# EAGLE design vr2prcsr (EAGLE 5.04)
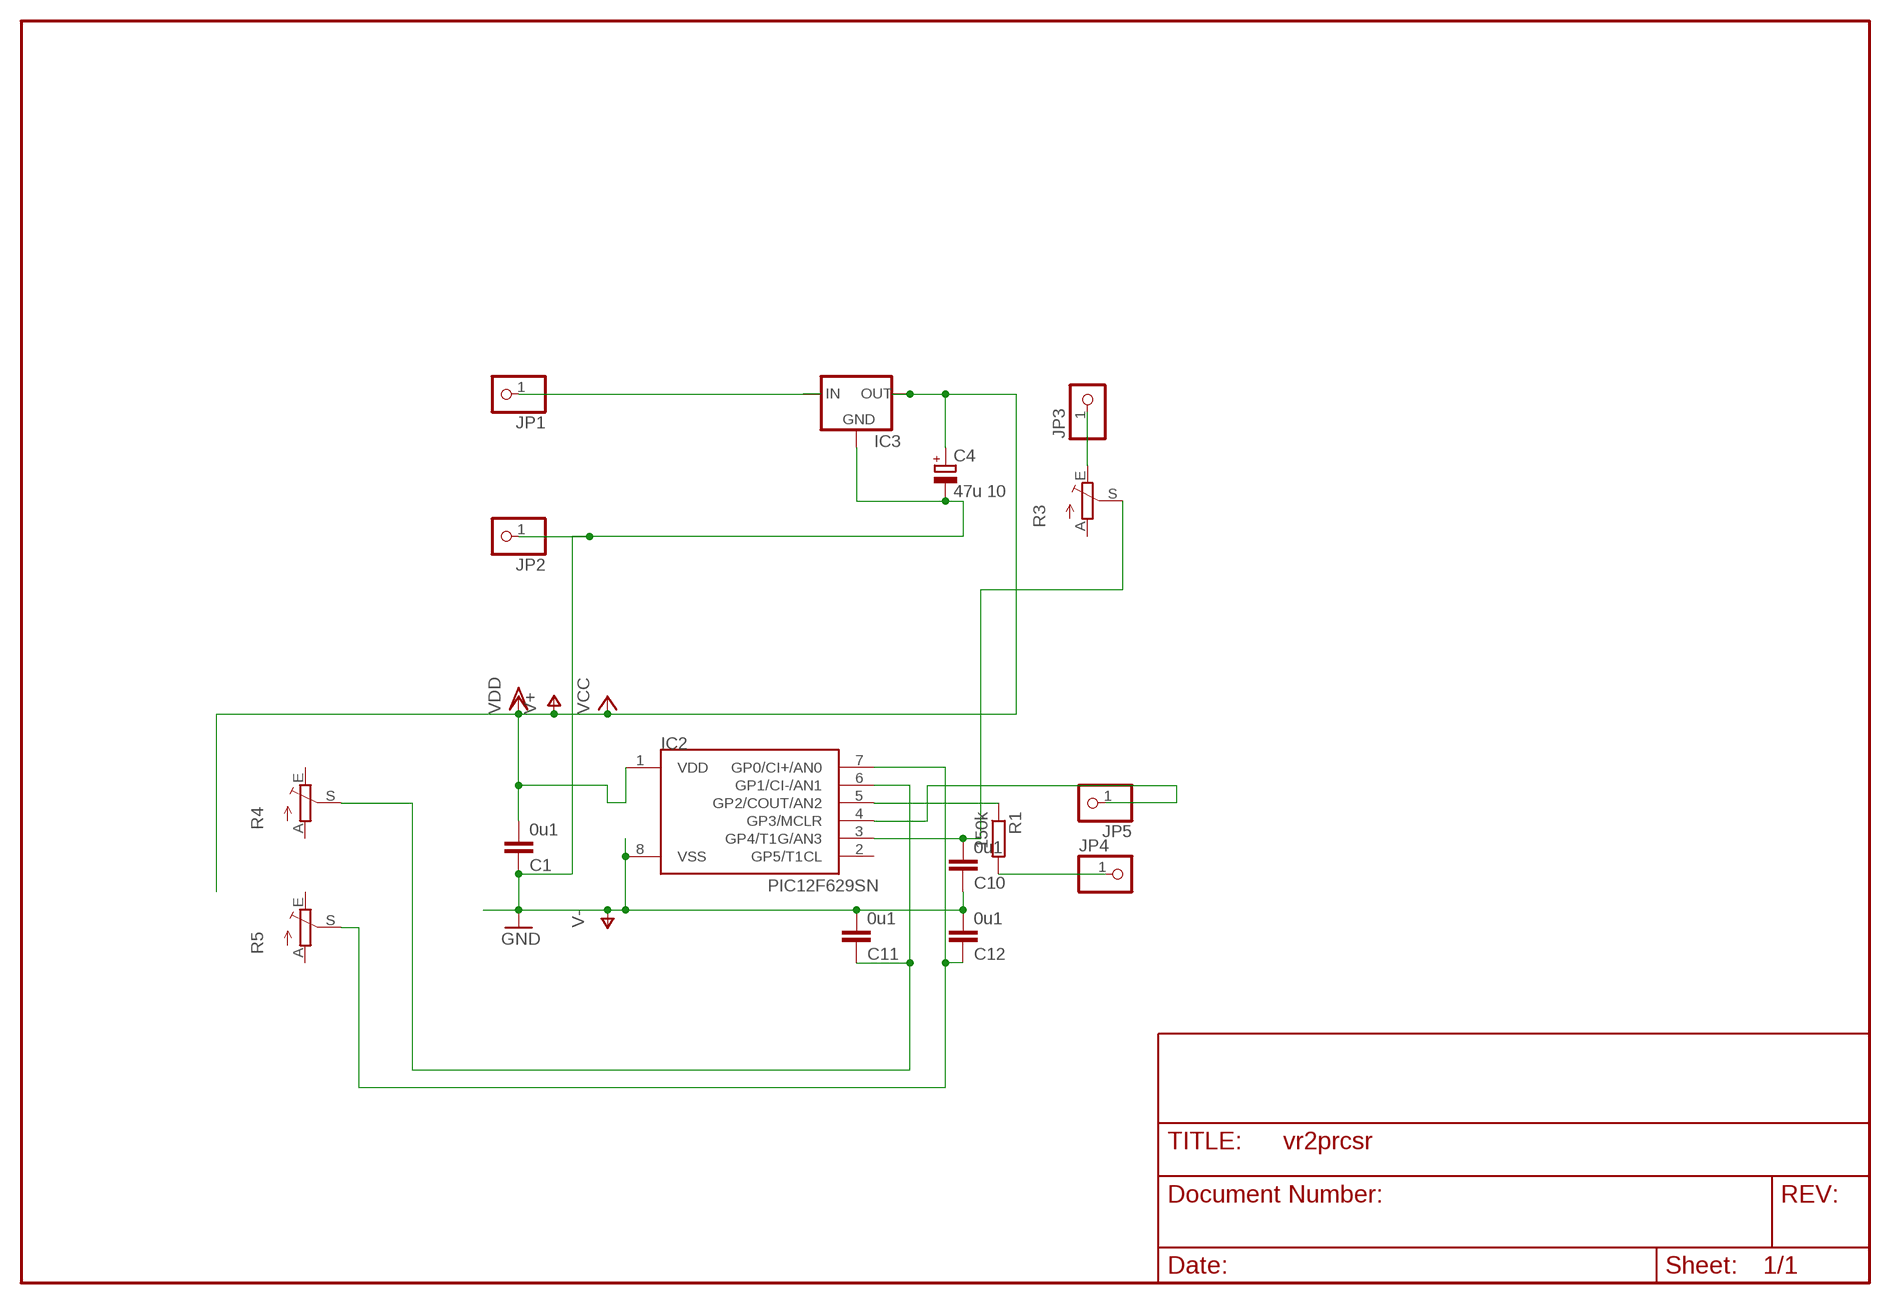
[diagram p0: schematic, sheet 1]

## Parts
C1  0u1  C-EUC1206  [C1206]
C4  47u 10  CPOL-EUE2.5-6  [E2,5-6]
C10  0u1  C-EUC1206  [C1206]
C11  0u1  C-EUC1206  [C1206]
C12  0u1  C-EUC1206  [C1206]
IC2  PIC12F629SN  [SO-08]
IC3  78LXX  [78LXX]
JP1  PINHD-1X1  [1X01]
JP2  PINHD-1X1  [1X01]
JP3  PINHD-1X1  [1X01]
JP4  PINHD-1X1  [1X01]
JP5  PINHD-1X1  [1X01]
R1  150k  R-EU_R1206  [R1206]
R3  TRIM_EU-CA6V  [CA6V]
R4  TRIM_EU-CA6V  [CA6V]
R5  TRIM_EU-CA6V  [CA6V]

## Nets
N$1: JP3.1 R3.E
N$2: JP4.1 R1.2
N$3: IC2.4(GP3/MCLR) JP5.1
N$5: IC2.5(GP2/COUT/AN2) R1.1
N$12: C10.2 IC2.3(GP4/T1G/AN3) R3.S
N$13: C12.1 IC2.7(GP0/CI+/AN0) R5.S
N$15: C11.1 IC2.6(GP1/CI-/AN1) R4.S
N$20: IC3.IN JP1.1
V+: C1.2 C4.+ IC2.1(VDD) IC3.OUT ; supply symbol labelled VCC, VDD
V-: C1.1 C4.- C10.1 C11.2 C12.2 IC2.8(VSS) IC3.GND JP2.1 ; supply symbol labelled GND
Unconnected: IC2.2(GP5/T1CL) R3.A R4.A R4.E R5.A R5.E

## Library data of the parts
C1 C10-C12 = rcl:C-EU: CAPACITOR, European symbol
C4 = rcl:CPOL-EU: POLARIZED CAPACITOR, European symbol
IC2 = microchip-3:PIC12F6*: uPC nW 1k Program Flash memory 2x Timer Comparator 10b A/D converter/ 4xIN
IC3 = v-reg:78LXX: VOLTAGE REGULATOR
JP1-JP5 = pinhead:PINHD-1X1: PIN HEADER
R1 = rcl:R-EU_: RESISTOR, European symbol
R3-R5 = pot:TRIM_EU-: POTENTIOMETER

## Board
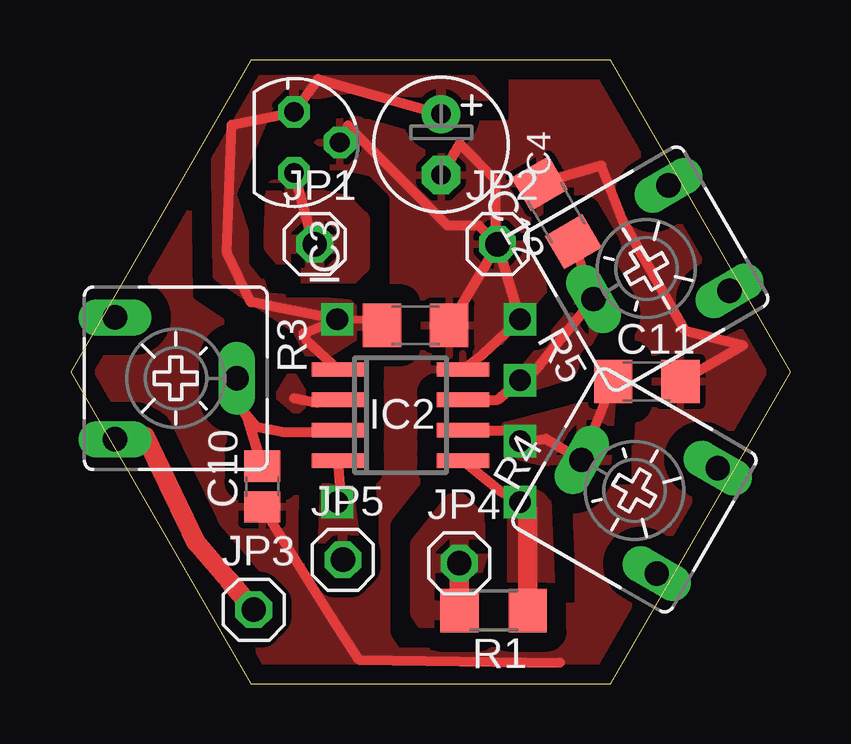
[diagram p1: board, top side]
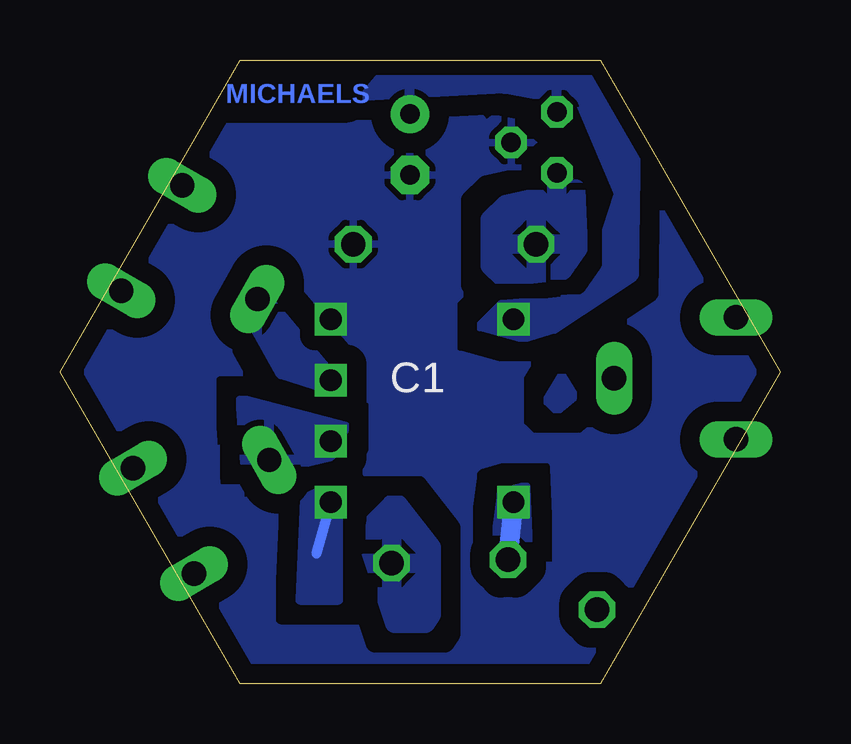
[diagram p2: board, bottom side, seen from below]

Size 30 x 26 mm. Coordinates in mm from the lower left corner, seen from the top.
Outline: 7.5,0 22.5,0 30,13 22.5,26 7.5,26 0,13 7.5,0
Copper layers (1*16): Top 0.035mm / dielectric 1.5mm / Bottom 0.035mm
Design rules "default *": minimum track width 10mil, minimum drill 24mil, track to track 8mil, track to pad 8mil, pad to pad 8mil, via to via 8mil, smd to smd 8mil, copper to edge 10mil, drill to drill 8mil, minimum pad ring 10mil, minimum via ring 8mil, stop-mask expansion 4mil, vias tented up to drill 0mil, thermal gap 10mil

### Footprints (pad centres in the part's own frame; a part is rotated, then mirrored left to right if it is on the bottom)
C1206 = smd 1.6 x 1.8: 1 -1.4,0; 2 1.4,0
E2,5-6 = drill 0.813 pad 1.6 round: + -1.27,0 | drill 0.813 pad 1.6 octagon: - 1.27,0
C0805 = smd 1.3 x 1.5: 1 -0.85,0; 2 0.85,0
SO-08 = smd 0.6 x 2.2: 1 -1.905,-2.6; 2 -0.635,-2.6; 3 0.635,-2.6; 4 1.905,-2.6; 5 1.905,2.6; 6 0.635,2.6; 7 -0.635,2.6; 8 -1.905,2.6
78LXX = drill 0.813 octagon: GND 0,1.905; IN 1.27,0; OUT -1.27,0
1X01 = drill 1.016 octagon: 1 0,0
R1206 = smd 1.6 x 1.803: 1 -1.422,0; 2 1.422,0
CA6V = drill 1.016 long: A -2.54,-2.54; E 2.54,-2.54; S 0,2.54

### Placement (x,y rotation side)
C1  14.36,14.94 180 top
C4  15.42,22.47 270 top
C10  0u1  [C0805]  7.97,8.21 90 top
C11  24,12.59 0 top
C12  20.23,19.63 120 top
IC2  13.74,11.19 270 top
IC3  9.3,22.56 270 top
JP1  10.16,18.32 0 top
JP2  17.78,18.32 0 top
JP3  7.62,3.08 0 top
JP4  16.18,5.02 0 top
JP5  11.33,5.16 0 top
R1  17.61,3.05 180 top
R3  4.37,12.73 270 top
R4  23.48,8.05 60 top
R5  23.98,17.3 120 top

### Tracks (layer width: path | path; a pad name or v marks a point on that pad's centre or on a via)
N$1
  Top 0.406: R3.E 3.1,10.3
  Top 0.813: 3.1,10.3 5.2,5.9 6.6,4.28 JP3.1
N$2
  Top 0.813: R1.2 JP4.1
  pour Top (isolate 0.813): 16.05,2.61 14.78,2.61 14.53,2.99 14.53,5.78 15.93,7.56 16.18,7.56 17.32,6.42
  pour Bottom (isolate 0.813): 16.05,2.51 14.78,2.51 14.53,2.89 14.53,5.68 15.93,7.46 16.18,7.46 17.32,6.32
N$3  (via drill 0.9)
  Top 0.406: IC2.4 11.26,7.72 v11.1,7.56
  Bottom 0.406: JP5.1 11.3,5.59
  Bottom 0.813: 11.3,5.59 v11.1,7.56
  pour Top (isolate 0.61): 10.6,8.2 11.6,7.9 11.9,5.6 11.3,5.4 10.5,5.7
  pour Bottom (isolate 0.61): 10.6,8.2 11.6,7.9 11.9,5.6 11.3,5.4 10.5,5.7
N$4
  pour Bottom (isolate 0.254): 9.7,11.8 9.3,11.4 8.6,12 9.1,12.8
N$5  (via drill 0.9)
  Top 0.406: IC2.5 17.88,8.02 v18.72,7.56
  Top 0.813: R1.1 19.04,7.24 v18.72,7.56
  Bottom 0.406: v18.72,7.56 19.32,5.42
  pour Top (isolate 0.61): 19,8.1 19.8,7.7 20,3.5 18.4,3.5 18.4,7
  pour Bottom (isolate 0.61): 19,8.1 19.8,7.7 20,3.5 18.4,3.5 18.4,7
N$7
  Top 0.406: 9.3,11.9 10.3,11.7
  pour Top (isolate 0.254): 9.8,11.8 9.4,11.4 8.7,12 9.2,12.8
N$12
  Top 0.406: 7.06,11.49 7.7,10.72 8.86,10.48 11.06,10.48 IC2.3 | 7.06,11.49 R3.S | C10.2 7.37,11.08 7.06,11.49
N$13  (via drill 0.9)
  Top 0.406: IC2.7 17.78,11.83 v18.72,12.64 19.19,13.11 | 18.8,12.5 19.4,13.1 R5.S C12.1
  pour Top (isolate 0.61): 18.9,12.3 20.8,12.9 22.3,15.6 21.5,16.2 18.3,12.4
  pour Bottom (isolate 0.61): 18.9,12.3 20.8,12.9 22.3,15.6 21.5,16.2 18.3,12.4
N$15  (via drill 0.9)
  Top 0.406: IC2.6 18.92,10.56 v18.72,10.1 | v18.72,10.1 18.83,9.99 | C11.1 R4.S 19.8,10.2 v18.72,10.1
  pour Top (isolate 0.61, rank 2): 18.1,10.7 22.3,11.8 22.5,11.8 22.3,9.2 21.6,8.8 18.7,9.5
  pour Bottom (isolate 0.61, rank 2): 18.1,10.7 22.3,11.8 22.5,11.8 22.3,9.2 21.6,8.8 18.7,9.5
N$20
  Top 0.406: IC3.IN 10.1,18.38 JP1.1
  pour Top (isolate 0.813): 8.51,20.61 8.41,18.28 9.36,17.12 11.56,16.92 12.06,17.43 12.06,19.34 11.43,19.97
  pour Bottom (isolate 0.813): 8.51,20.61 8.41,18.18 9.06,17.22 11.56,16.92 12.06,17.43 12.06,19.34 11.43,19.97
V+  (via drill 0.9)
  Top 0.305: v11.1,15.18 13.35,15.18 C1.2
  Top 0.406: IC2.1 9.83,14.3 9.7,14.6 v11.1,15.18 7.5,15.9 6.5,18 6.7,23.3 IC3.OUT 10.3,25.2 C4.+
  pour Top (isolate 0.61, rank 2): 16.1,25.9 8,25.9 6,24.1 6.1,17 9.4,14.8 10.1,13.4 12.5,14.9 11.6,15.8 8.1,16.1 6.7,20.4 8.3,24.2 11.5,24.8 17.3,24.5
  pour Bottom (isolate 0.61, rank 2): 16.1,25.9 8,25.9 6,24.1 6.1,17 9.4,14.8 10.7,14.4 12.5,14.9 11.6,15.8 8.1,16.1 6.7,20.4 8.3,24.2 11.5,24.8 17.3,24.5
V-  (via drill 0.9)
  Top 0.406: IC2.8 17.16,13.72 v18.72,15.18 JP2.1 | IC3.GND 11.54,23.26 15.7,19.1 17,19.1 JP2.1 | C4.- 16.2,22.5 17.7,21 17.7,18.4 JP2.1 | JP2.1 C1.1 | C11.2 28,14.1 25.6,14.7 23,19.3 22.1,21.6 C12.2 | C10.1 10.9,2.7 12,1 20.37,0.87
  pour Top (isolate 0.813, rank 4): 12.24,23.35 15.23,26.55 24.4,26.18 25.15,20.48 26.18,21.21 28.48,18.56 31.06,13.58 23.09,-0.65 7.34,-0.25 -0.28,12.57 4.82,21.74 7.51,26.64
  pour Bottom (isolate 0.813, rank 4): 12.24,23.35 15.23,26.55 24.4,26.18 25.15,20.48 26.18,21.21 28.48,18.56 31.06,13.58 23.09,-0.65 7.34,-0.25 -0.28,12.57 4.82,21.74 7.51,26.64

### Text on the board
Bottom: MICHAELS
